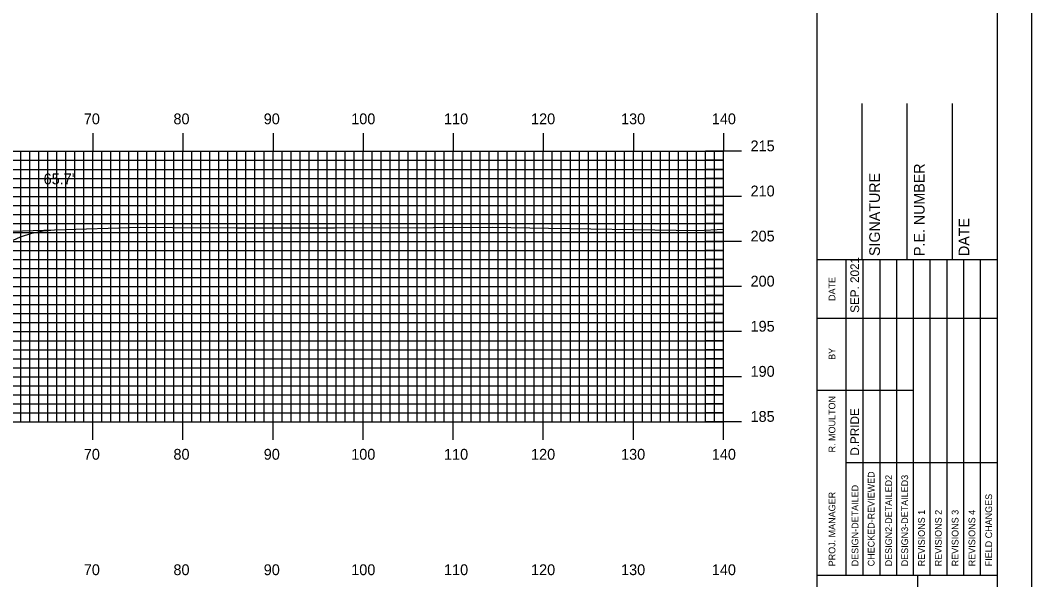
# Model space of a CAD drawing. Extents: x 1799568 to 1799912, y 442591 to 442811.
# Drawn here: x 1799796 to 1799908.2, y 442686.2 to 442748.2 of the extents above; entities that cross this region are included whole.
import ezdxf

# ---------------------------------------------------------------- set-up
doc = ezdxf.new("R2010")
doc.units = 0
for name, color, linetype in [('BORDER', 7, 'Continuous'), ('D_Roadway_Centerline', 7, 'Continuous'), ('D_Roadway_SlopeLines', 7, 'Continuous'), ('D_Text_Standard', 7, 'Continuous'), ('H_V ANNOTATION', 7, 'Continuous'), ('MAJOR', 7, 'Continuous'), ('MINOR', 7, 'Continuous'), ('PLOT BOUNDARY', 7, 'Continuous'), ('S_Roadway_Centerline', 7, 'Continuous')]:
    doc.layers.add(name, color=color, linetype=linetype)

msp = doc.modelspace()

# ---------------------------------------------------------------- linework, layer by layer
at = {"layer": 'BORDER'}
for p, q in [((1799884.41, 442596.67), (1799884.41, 442806.67)), ((1799889.41, 442721.67), (1799889.41, 442738.97)), ((1799894.41, 442721.67), (1799894.41, 442738.97)), ((1799899.41, 442721.67), (1799899.41, 442738.97)), ((1799884.41, 442721.67), (1799904.41, 442721.67)), ((1799884.41, 442686.67), (1799904.41, 442686.67)), ((1799895.59, 442616.67), (1799895.59, 442686.67))]:
    msp.add_line(p, q, dxfattribs=at)
msp.add_lwpolyline([(1799584.41, 442596.67), (1799904.41, 442596.67), (1799904.41, 442806.67), (1799584.41, 442806.67)], close=True, dxfattribs=at)
for points in [[(1799887.64, 442715.17), (1799887.64, 442721.67)], [(1799889.5, 442686.68), (1799889.5, 442721.67)], [(1799891.37, 442721.67), (1799891.37, 442686.68)], [(1799893.23, 442686.68), (1799893.23, 442721.67)], [(1799895.1, 442686.68), (1799895.1, 442721.67)], [(1799896.96, 442686.68), (1799896.96, 442721.67)], [(1799898.82, 442686.68), (1799898.82, 442721.67)], [(1799900.69, 442686.68), (1799900.69, 442721.67)], [(1799902.55, 442686.68), (1799902.55, 442721.67)], [(1799887.64, 442686.68), (1799887.64, 442720.26)], [(1799884.41, 442715.17), (1799904.41, 442715.17)], [(1799884.41, 442707.17), (1799887.64, 442707.17)], [(1799887.64, 442707.17), (1799895.09, 442707.17)], [(1799887.64, 442699.17), (1799904.41, 442699.17)]]:
    msp.add_lwpolyline(points, dxfattribs=at)
at = {"layer": 'D_Roadway_Centerline'}
msp.add_lwpolyline([(1799674.31, 442722.27), (1799675.56, 442722.22), (1799676.81, 442722.01), (1799678.06, 442721.63), (1799679.31, 442721.09), (1799699.84, 442710.83), (1799703.84, 442711.83), (1799714.01, 442714.37), (1799722.01, 442714.69), (1799734.01, 442714.45), (1799746.01, 442714.21), (1799754.01, 442713.89), (1799764.18, 442711.35), (1799768.18, 442710.35), (1799794.75, 442723.63), (1799796, 442724.18), (1799797.25, 442724.58), (1799798.5, 442724.84), (1799799.75, 442724.95)], dxfattribs=at)
at = {"layer": 'D_Roadway_SlopeLines'}
msp.add_lwpolyline([(1799768.18, 442710.35), (1799794.75, 442723.63), (1799796, 442724.18), (1799797.25, 442724.58), (1799798.5, 442724.84), (1799799.75, 442724.95)], dxfattribs=at)
at = {"layer": 'MAJOR'}
for p, q in [((1799804.01, 442735.67), (1799804.01, 442733.67)), ((1799814.01, 442735.67), (1799814.01, 442733.67)), ((1799824.01, 442735.67), (1799824.01, 442733.67)), ((1799834.01, 442735.67), (1799834.01, 442733.67)), ((1799844.01, 442735.67), (1799844.01, 442733.67)), ((1799854.01, 442735.67), (1799854.01, 442733.67)), ((1799864.01, 442735.67), (1799864.01, 442733.67)), ((1799874.01, 442735.67), (1799874.01, 442733.67)), ((1799594.01, 442733.67), (1799874.01, 442733.67)), ((1799594.01, 442733.67), (1799874.01, 442733.67)), ((1799804.01, 442703.67), (1799804.01, 442733.67)), ((1799814.01, 442703.67), (1799814.01, 442733.67)), ((1799824.01, 442703.67), (1799824.01, 442733.67)), ((1799834.01, 442703.67), (1799834.01, 442733.67)), ((1799844.01, 442703.67), (1799844.01, 442733.67)), ((1799854.01, 442703.67), (1799854.01, 442733.67)), ((1799864.01, 442703.67), (1799864.01, 442733.67)), ((1799876.01, 442733.67), (1799872.01, 442733.67)), ((1799874.01, 442703.67), (1799874.01, 442733.67)), ((1799874.01, 442703.67), (1799874.01, 442733.67)), ((1799594.01, 442728.67), (1799874.01, 442728.67)), ((1799876.01, 442728.67), (1799872.01, 442728.67)), ((1799594.01, 442723.67), (1799874.01, 442723.67)), ((1799876.01, 442723.67), (1799872.01, 442723.67)), ((1799594.01, 442718.67), (1799874.01, 442718.67)), ((1799876.01, 442718.67), (1799872.01, 442718.67)), ((1799594.01, 442713.67), (1799874.01, 442713.67)), ((1799876.01, 442713.67), (1799872.01, 442713.67)), ((1799594.01, 442708.67), (1799874.01, 442708.67)), ((1799876.01, 442708.67), (1799872.01, 442708.67)), ((1799594.01, 442703.67), (1799874.01, 442703.67)), ((1799594.01, 442703.67), (1799874.01, 442703.67)), ((1799804.01, 442701.66), (1799804.01, 442703.67)), ((1799814.01, 442701.66), (1799814.01, 442703.67)), ((1799824.01, 442701.66), (1799824.01, 442703.67)), ((1799834.01, 442701.66), (1799834.01, 442703.67)), ((1799844.01, 442701.66), (1799844.01, 442703.67)), ((1799854.01, 442701.66), (1799854.01, 442703.67)), ((1799864.01, 442701.66), (1799864.01, 442703.67)), ((1799876.01, 442703.67), (1799872.01, 442703.67)), ((1799874.01, 442701.66), (1799874.01, 442703.67))]:
    msp.add_line(p, q, dxfattribs=at)
at = {"layer": 'MINOR'}
for p, q in [((1799796.01, 442703.67), (1799796.01, 442733.67)), ((1799797.01, 442703.67), (1799797.01, 442733.67)), ((1799798.01, 442703.67), (1799798.01, 442733.67)), ((1799799.01, 442703.67), (1799799.01, 442733.67)), ((1799800.01, 442703.67), (1799800.01, 442733.67)), ((1799801.01, 442703.67), (1799801.01, 442733.67)), ((1799802.01, 442703.67), (1799802.01, 442733.67)), ((1799803.01, 442703.67), (1799803.01, 442733.67)), ((1799805.01, 442703.67), (1799805.01, 442733.67)), ((1799806.01, 442703.67), (1799806.01, 442733.67)), ((1799807.01, 442703.67), (1799807.01, 442733.67)), ((1799808.01, 442703.67), (1799808.01, 442733.67)), ((1799809.01, 442703.67), (1799809.01, 442733.67)), ((1799810.01, 442703.67), (1799810.01, 442733.67)), ((1799811.01, 442703.67), (1799811.01, 442733.67)), ((1799812.01, 442703.67), (1799812.01, 442733.67)), ((1799813.01, 442703.67), (1799813.01, 442733.67)), ((1799815.01, 442703.67), (1799815.01, 442733.67)), ((1799816.01, 442703.67), (1799816.01, 442733.67)), ((1799817.01, 442703.67), (1799817.01, 442733.67)), ((1799818.01, 442703.67), (1799818.01, 442733.67)), ((1799819.01, 442703.67), (1799819.01, 442733.67)), ((1799820.01, 442703.67), (1799820.01, 442733.67)), ((1799821.01, 442703.67), (1799821.01, 442733.67)), ((1799822.01, 442703.67), (1799822.01, 442733.67)), ((1799823.01, 442703.67), (1799823.01, 442733.67)), ((1799825.01, 442703.67), (1799825.01, 442733.67)), ((1799826.01, 442703.67), (1799826.01, 442733.67)), ((1799827.01, 442703.67), (1799827.01, 442733.67)), ((1799828.01, 442703.67), (1799828.01, 442733.67)), ((1799829.01, 442703.67), (1799829.01, 442733.67)), ((1799830.01, 442703.67), (1799830.01, 442733.67)), ((1799831.01, 442703.67), (1799831.01, 442733.67)), ((1799832.01, 442703.67), (1799832.01, 442733.67)), ((1799833.01, 442703.67), (1799833.01, 442733.67)), ((1799835.01, 442703.67), (1799835.01, 442733.67)), ((1799836.01, 442703.67), (1799836.01, 442733.67)), ((1799837.01, 442703.67), (1799837.01, 442733.67)), ((1799838.01, 442703.67), (1799838.01, 442733.67)), ((1799839.01, 442703.67), (1799839.01, 442733.67)), ((1799840.01, 442703.67), (1799840.01, 442733.67)), ((1799841.01, 442703.67), (1799841.01, 442733.67)), ((1799842.01, 442703.67), (1799842.01, 442733.67)), ((1799843.01, 442703.67), (1799843.01, 442733.67)), ((1799845.01, 442703.67), (1799845.01, 442733.67)), ((1799846.01, 442703.67), (1799846.01, 442733.67)), ((1799847.01, 442703.67), (1799847.01, 442733.67)), ((1799848.01, 442703.67), (1799848.01, 442733.67)), ((1799849.01, 442703.67), (1799849.01, 442733.67)), ((1799850.01, 442703.67), (1799850.01, 442733.67)), ((1799851.01, 442703.67), (1799851.01, 442733.67)), ((1799852.01, 442703.67), (1799852.01, 442733.67)), ((1799853.01, 442703.67), (1799853.01, 442733.67)), ((1799855.01, 442703.67), (1799855.01, 442733.67)), ((1799856.01, 442703.67), (1799856.01, 442733.67)), ((1799857.01, 442703.67), (1799857.01, 442733.67)), ((1799858.01, 442703.67), (1799858.01, 442733.67)), ((1799859.01, 442703.67), (1799859.01, 442733.67)), ((1799860.01, 442703.67), (1799860.01, 442733.67)), ((1799861.01, 442703.67), (1799861.01, 442733.67)), ((1799862.01, 442703.67), (1799862.01, 442733.67)), ((1799863.01, 442703.67), (1799863.01, 442733.67)), ((1799865.01, 442703.67), (1799865.01, 442733.67)), ((1799866.01, 442703.67), (1799866.01, 442733.67)), ((1799867.01, 442703.67), (1799867.01, 442733.67)), ((1799868.01, 442703.67), (1799868.01, 442733.67)), ((1799869.01, 442703.67), (1799869.01, 442733.67)), ((1799870.01, 442703.67), (1799870.01, 442733.67)), ((1799871.01, 442703.67), (1799871.01, 442733.67)), ((1799872.01, 442703.67), (1799872.01, 442733.67)), ((1799873.01, 442703.67), (1799873.01, 442733.67)), ((1799594.01, 442732.67), (1799874.01, 442732.67)), ((1799874.01, 442732.67), (1799872.01, 442732.67)), ((1799594.01, 442731.67), (1799874.01, 442731.67)), ((1799874.01, 442731.67), (1799872.01, 442731.67)), ((1799594.01, 442730.67), (1799874.01, 442730.67)), ((1799594.01, 442729.67), (1799874.01, 442729.67)), ((1799874.01, 442730.67), (1799872.01, 442730.67)), ((1799874.01, 442729.67), (1799872.01, 442729.67)), ((1799594.01, 442727.67), (1799874.01, 442727.67)), ((1799874.01, 442727.67), (1799872.01, 442727.67)), ((1799594.01, 442726.67), (1799874.01, 442726.67)), ((1799874.01, 442726.67), (1799872.01, 442726.67)), ((1799594.01, 442725.67), (1799874.01, 442725.67)), ((1799874.01, 442725.67), (1799872.01, 442725.67)), ((1799594.01, 442724.67), (1799874.01, 442724.67)), ((1799874.01, 442724.67), (1799872.01, 442724.67)), ((1799594.01, 442722.67), (1799874.01, 442722.67)), ((1799874.01, 442722.67), (1799872.01, 442722.67)), ((1799594.01, 442721.67), (1799874.01, 442721.67)), ((1799594.01, 442720.67), (1799874.01, 442720.67)), ((1799874.01, 442721.67), (1799872.01, 442721.67)), ((1799874.01, 442720.67), (1799872.01, 442720.67)), ((1799594.01, 442719.67), (1799874.01, 442719.67)), ((1799874.01, 442719.67), (1799872.01, 442719.67)), ((1799594.01, 442717.67), (1799874.01, 442717.67)), ((1799874.01, 442717.67), (1799872.01, 442717.67)), ((1799594.01, 442716.67), (1799874.01, 442716.67)), ((1799874.01, 442716.67), (1799872.01, 442716.67)), ((1799594.01, 442715.67), (1799874.01, 442715.67)), ((1799874.01, 442715.67), (1799872.01, 442715.67)), ((1799594.01, 442714.67), (1799874.01, 442714.67)), ((1799874.01, 442714.67), (1799872.01, 442714.67)), ((1799594.01, 442712.67), (1799874.01, 442712.67)), ((1799874.01, 442712.67), (1799872.01, 442712.67)), ((1799594.01, 442711.67), (1799874.01, 442711.67)), ((1799594.01, 442710.67), (1799874.01, 442710.67)), ((1799874.01, 442711.67), (1799872.01, 442711.67)), ((1799874.01, 442710.67), (1799872.01, 442710.67)), ((1799594.01, 442709.67), (1799874.01, 442709.67)), ((1799874.01, 442709.67), (1799872.01, 442709.67)), ((1799594.01, 442707.67), (1799874.01, 442707.67)), ((1799874.01, 442707.67), (1799872.01, 442707.67)), ((1799594.01, 442706.67), (1799874.01, 442706.67)), ((1799874.01, 442706.67), (1799872.01, 442706.67)), ((1799594.01, 442705.67), (1799874.01, 442705.67)), ((1799874.01, 442705.67), (1799872.01, 442705.67)), ((1799594.01, 442704.67), (1799874.01, 442704.67)), ((1799874.01, 442704.67), (1799872.01, 442704.67))]:
    msp.add_line(p, q, dxfattribs=at)
at = {"layer": 'PLOT BOUNDARY'}
msp.add_lwpolyline([(1799568.22, 442590.55), (1799908.22, 442590.55), (1799908.22, 442810.55), (1799568.22, 442810.55)], close=True, dxfattribs=at)
at = {"layer": 'S_Roadway_Centerline'}
msp.add_lwpolyline([(1799790.22, 442724.67), (1799809.27, 442725.24), (1799812.87, 442725.23), (1799819.97, 442725.19), (1799830.84, 442725.19), (1799841.81, 442725.23), (1799848.35, 442725.24), (1799854.58, 442725.14), (1799863.98, 442724.99), (1799871.16, 442724.9), (1799874.01, 442725.04)], dxfattribs=at)

# ---------------------------------------------------------------- texts
at = {"layer": 'BORDER'}
for s, height, p in [('P.E. NUMBER', 1.1811, (1799896.33, 442722.06)), ('SIGNATURE', 1.181, (1799891.37, 442722.06)), ('DATE', 1.181, (1799901.29, 442722.06)), ('SEP. 2021', 0.969, (1799889.06, 442715.76)), ('DATE', 0.743, (1799886.42, 442717.08)), ('BY', 0.743, (1799886.42, 442710.54)), ('R. MOULTON', 0.745, (1799886.42, 442700.28)), ('D.PRIDE', 0.969, (1799889.06, 442699.92)), ('CHECKED-REVIEWED', 0.7455, (1799890.77, 442687.65)), ('DESIGN2-DETAILED2', 0.7455, (1799892.71, 442687.65)), ('DESIGN3-DETAILED3', 0.7455, (1799894.5, 442687.65)), ('DESIGN-DETAILED', 0.7455, (1799888.98, 442687.65)), ('PROJ. MANAGER', 0.7455, (1799886.42, 442687.65)), ('FIELD CHANGES', 0.7455, (1799903.82, 442687.65)), ('REVISIONS 1', 0.7455, (1799896.36, 442687.65)), ('REVISIONS 2', 0.7455, (1799898.23, 442687.65)), ('REVISIONS 3', 0.7455, (1799900.09, 442687.65)), ('REVISIONS 4', 0.7455, (1799901.95, 442687.65))]:
    msp.add_text(s, height=height, rotation=90, dxfattribs=at).set_placement(p)
at = {"layer": 'D_Text_Standard'}
msp.add_text("65.7'", height=1.2, dxfattribs=at).set_placement((1799798.55, 442730.01))
at = {"layer": 'H_V ANNOTATION'}
for s, p in [('70', (1799803.01, 442736.67)), ('80', (1799812.96, 442736.67)), ('90', (1799822.98, 442736.67)), ('100', (1799832.69, 442736.67)), ('110', (1799842.99, 442736.67)), ('120', (1799852.65, 442736.67)), ('130', (1799862.64, 442736.67)), ('140', (1799872.71, 442736.67)), ('215', (1799877.01, 442733.67)), ('210', (1799877.01, 442728.67)), ('205', (1799877.01, 442723.67)), ('200', (1799877.01, 442718.67)), ('195', (1799877.01, 442713.67)), ('190', (1799877.01, 442708.67)), ('185', (1799877.01, 442703.67)), ('70', (1799803.01, 442699.47)), ('80', (1799812.96, 442699.47)), ('90', (1799822.98, 442699.47)), ('100', (1799832.69, 442699.47)), ('110', (1799842.99, 442699.47)), ('120', (1799852.65, 442699.47)), ('130', (1799862.64, 442699.47)), ('140', (1799872.71, 442699.47)), ('70', (1799803.01, 442686.67)), ('80', (1799812.96, 442686.67)), ('90', (1799822.98, 442686.67)), ('100', (1799832.69, 442686.67)), ('110', (1799842.99, 442686.67)), ('120', (1799852.65, 442686.67)), ('130', (1799862.64, 442686.67)), ('140', (1799872.71, 442686.67))]:
    msp.add_text(s, height=1.2, dxfattribs=at).set_placement(p)

doc.saveas('drawing.dxf')
